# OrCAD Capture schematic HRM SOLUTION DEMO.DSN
size B; title: PSoC 4 BLE HRM Solution Demo; note: -
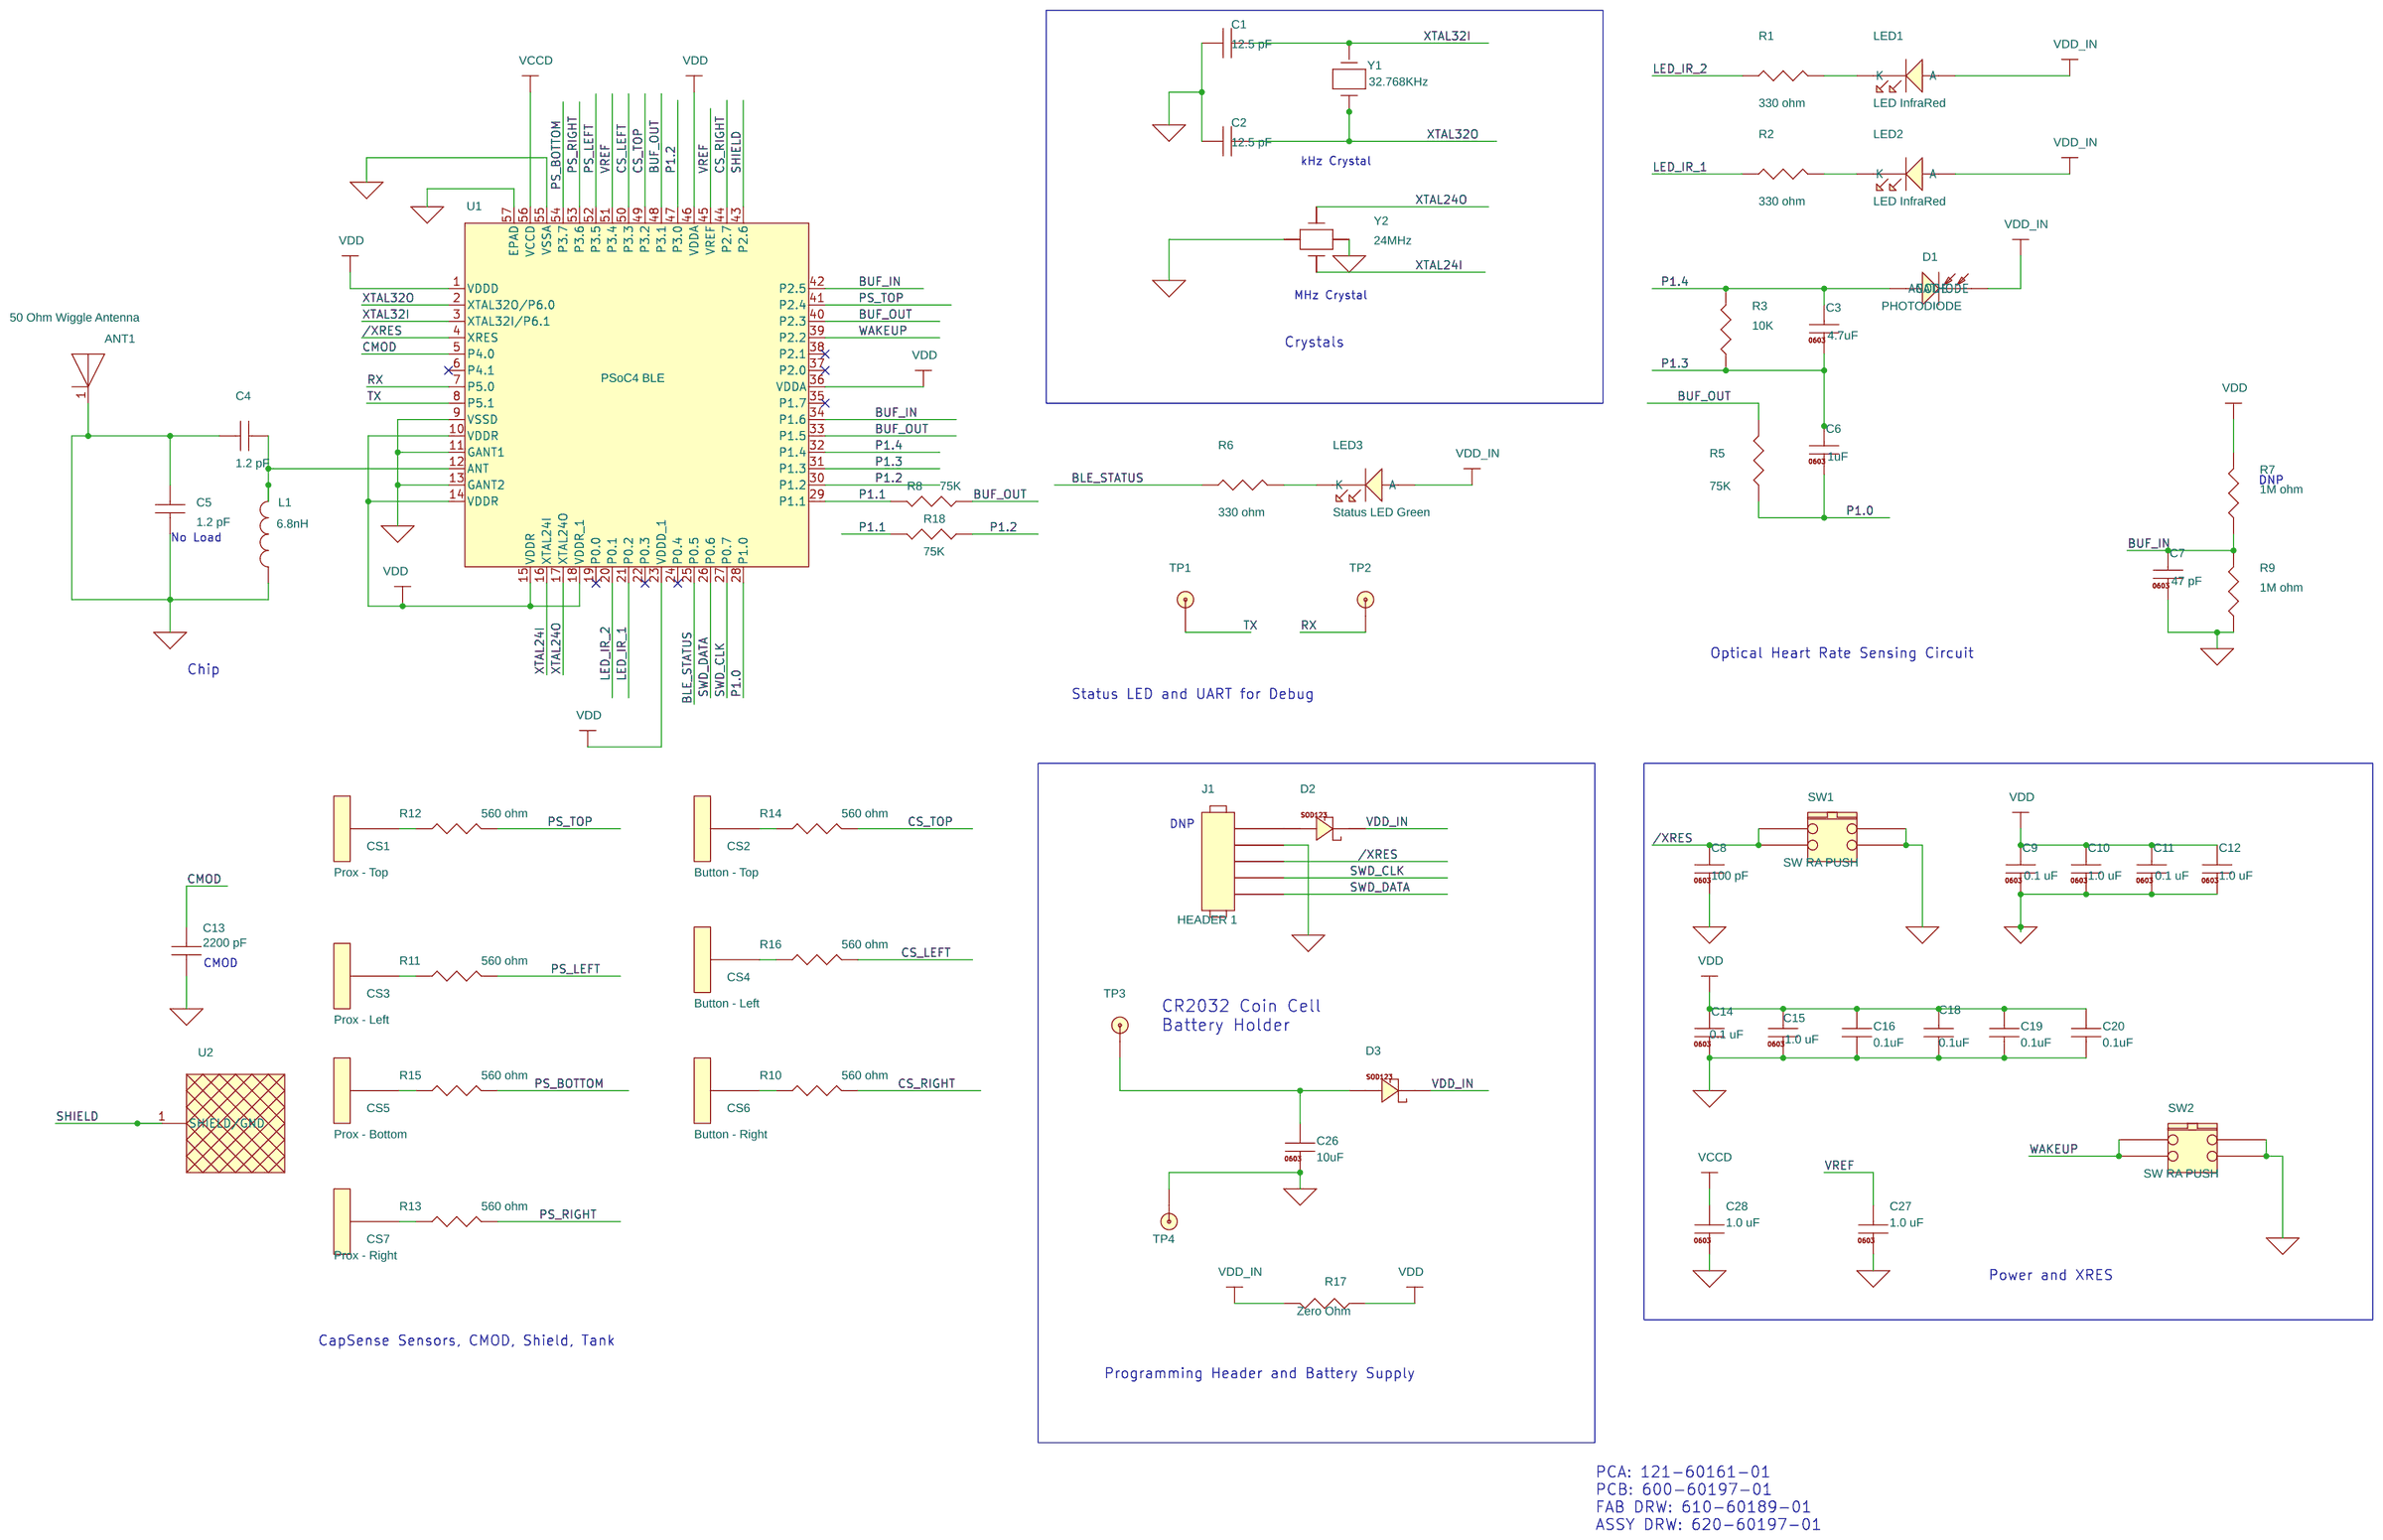
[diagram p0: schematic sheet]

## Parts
ANT1  50 Ohm Wiggle Antenna  [antenna15]
C1  12.5 pF  [C-CC0603]
C2  12.5 pF  [C-CC0603]
C3  4.7uF  [C-CC0603]
C4  1.2 pF  [cc0402]
C5  1.2 pF  [cc0402_1]
C6  1uF  [C-CC0603]
C7  47 pF  [C-CC0603]
C8  100 pF  [C-CC0603]
C9  0.1 uF  [c-cc0402]
C10  1.0 uF  [C-CC0603]
C11  0.1 uF  [c-cc0402]
C12  1.0 uF  [C-CC0603]
C13  2200 pF  [C-CC0603]
C14  0.1 uF  [c-cc0402]
C15  1.0 uF  [C-CC0603]
C16  0.1uF  [C-CC0603]
C18  0.1uF  [C-CC0603]
C19  0.1uF  [C-CC0603]
C20  0.1uF  [C-CC0603]
C26  10uF  [C-CC0603]
C27  1.0 uF  [C-CC0603]
C28  1.0 uF  [C-CC0603]
CS1  Prox - Top  [CAPSENCE]
CS2  Button - Top  [CAPSENCE]
CS3  Prox - Left  [CAPSENCE]
CS4  Button - Left  [CAPSENCE]
CS5  Prox - Bottom  [CAPSENCE]
CS6  Button - Right  [CAPSENCE]
CS7  Prox - Right  [CAPSENCE]
D1  PHOTODIODE  [PHOTO_DIODE]
D2  MBR0520L  [sod123]
D3  MBR0520L  [sod123]
J1  HEADER 1  [HEAD_5_2p54_40X80_420]
L1  6.8nH  [cc0402_1]
LED1  LED InfraRed  [LED]
LED2  LED InfraRed  [LED]
LED3  Status LED Green  [L0805]
R1  330 ohm  [R-CR0603]
R2  330 ohm  [R-CR0603]
R3  10K  [R-CR0603]
R5  75K  [R-CR0603]
R6  330 ohm  [R-CR0603]
R7  1M ohm  [R-CR0603]
R8  75K  [R0402-IPC]
R9  1M ohm  [R-CR0603]
R10  560 ohm  [R0402-IPC]
R11  560 ohm  [R0402-IPC]
R12  560 ohm  [R0402-IPC]
R13  560 ohm  [R0402-IPC]
R14  560 ohm  [R0402-IPC]
R15  560 ohm  [R0402-IPC]
R16  560 ohm  [R0402-IPC]
R17  Zero Ohm  [R-CR0603]
R18  75K  [R0402-IPC]
SW1  SW RA PUSH  [sw_4p_3p6_52x42_54]
SW2  SW RA PUSH  [sw_4p_3p6_52x42_54]
TP1  RED  [TP_48]
TP2  RED  [TP_48]
TP3  RED  [TP_48]
TP4  RED  [TP_48]
U1  PSoC4 BLE  [QFN40P700X700X60-57T570X570N]
U2  HASH GND  [VIA_25X13_SHIELD]
Y1  32.768KHz  [CRY_2_2P6_40X62_32]
Y2  24MHz  [CRY_4_1P7_80X100_22]

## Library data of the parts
ANT1 = Wiggle_Antenna_0
C1 C2 = CAP_NP: CAP CER 12PF 50V 5% NP0 0603; Manufacturer: TDK CORPORATION; Manufacturer Part No: C1608C0G1H120J080AA
C3 C6 C7 = 0_0.1_uFd_0402: CAP CER 47PF 50V 5% NP0 0603; ALT_SYMBOLS: C-CC0603_A; Mfr_Name: TDK CORPORATION; Mfr_Part_Number: C1608C0G1H470J080AA; VOLTAGE: 50V
C4 C5 = CAP: CAP CER 1.2PF 50V NP0 0603; Mfr_Name: SAMSUNG ELECTRO-MECHANICS AMERICA, INC (VA); Mfr_Part_Number: CL10C1R2CB8NNNC; Tolerance: 0.05pF
C8 = 1_0.0_uFd_0603_X5R_25V_10%: CAP CER 100PF 50V 5% NP0 0603; DEVICE: 100pFd_0603 _25V; Mfr_Name: TDK CORPORATION; Mfr_Part_Number: C1608C0G1H101J080AA; Tolerance: 5%; VOLTAGE: 50V
C9 C11 C14 = 0_0.1_uFd_0402: CAP CER 0.1UF 25V 10% X7R 0603; ALT_SYMBOLS: C-CC0603_A; DEVICE: 0p1uFd_0603; Mfr_Name: TDK CORPORATION; Mfr_Part_Number: C1608X7R1E104K080AA; Section: PSoC 4A; VOLTAGE: 25V
C10 C15 C27 C28 = 1_0.0_uFd_0603_X5R_25V_10%: CAP CER 1UF 25V 10% X5R 0603; Mfr_Name: TDK CORPORATION; Mfr_Part_Number: C1608X5R1E105K080AC; VOLTAGE: 25V
C12 = 1_0.0_uFd_0603_X5R_25V_10%: CAP CER 1UF 25V 10% X5R 0603; Mfr_Name: TDK CORPORATION; Mfr_Part_Number: C1608X5R1E105K080AC; Section: PSoC 4A; VOLTAGE: 25V
C13 = CAP: CAP CER 2200PF 50V 10% X7R 0603; Mfr_Name: SAMSUNG ELECTRO-MECHANICS AMERICA, INC (VA); Mfr_Part_Number: CL10B222KB8SFNC; Tolerance: 5%
C16 C18-C20 = CAPACITOR_NON-POL
C26 = 1_0.0_uFd_0603_X5R_25V_10%: CAP CER 10UF 16V 20% X5R 0603; DEVICE: 10uFd_0603_16V; Mfr_Name: MURATA ELECTRONICS; Mfr_Part_Number: GRM188R61C106MA73D; Tolerance: 20%; VOLTAGE: 16V
CS1-CS7 = CapSense_Sensor_0
D1 = PHOTODIODE_1
D2 D3 = TMP_134158: DIODE SCHOTTKY 20V 0.5A SOD123; Digikey: MBR0520LCT-ND
J1 = HEADER_5
L1 = INDUCTOR
LED1 LED2 = LED_Green_0805_0: LED 2.0X1.2MM IR WTR CLEAR 0805; Mfr_Name: SUNLED COMPANY LLC; Mfr_Part_Number: XZTNI54W
LED3 = LED_Green_0805_0: LED GREEN CLEAR 0805 SMD; Mfr_Name: VISUAL COMMUNICATIONS COMPANY, LLC; Mfr_Part_Number: CMD17-21VGC/TR8
R1 R2 = 330_ohm_5%_0805_1: RES 330 OHM 1/10W 5% 0603 SMD; DEVICE: 330oh_0603; Mfr_Name: PANASONIC ELECTRONIC COMPONENTS; Mfr_Part_Number: ERJ-3GEYJ331V; Section: User Interface
R3 R5 R7-R9 R18 = 330_ohm_5%_0805_1: RES 330 OHM 1/10W 5% 0603 SMD; Mfr_Name: PANASONIC ELECTRONIC COMPONENTS; Mfr_Part_Number: ERJ-3GEYJ331V; Section: User Interface
R6 = 330_ohm_5%_0805_1: RES 330 OHM 1/10W 5% 0603 SMD; DEVICE: 330ohm_0603; Mfr_Name: PANASONIC ELECTRONIC COMPONENTS; Mfr_Part_Number: ERJ-3GEYJ331V; Section: User Interface
R10-R16 = RESISTOR: RES 560 OHM 1/10W 5% 0603 SMD; CLASS: DISCRETE; DEVICE: 560_0603; Mfr_Name: Panasonic-ECG; Mfr_Part_Number: ERJ-3GEYJ561V
R17 = 330_ohm_5%_0805_0: RES 0.0 OHM 1/10W JUMP 0603 SMD; Mfr_Name: PANASONIC ELECTRONIC COMPONENTS; Mfr_Part_Number: ERJ-3GEY0R00V; Section: PSoC 4A
SW1 SW2 = Switch_RA_Pushbutton_0: SWITCH TACTILE SPST-NO 0.05A 12V; Mfr_Name: PANASONIC ELECTRONIC COMPONENTS; Mfr_Part_Number: EVQ-P7J01P
TP1-TP4 = TEST_POINT: TEST POINT 43 HOLE 65 PLATED RED; CLASS: DISCRETE; DEVICE: TP-43R_R; Mfr_Name: Keystone Electronics; Mfr_Part_Number: 5000; Package Type: TH; Part Number: 400-00001
U1 = PSoC_BLE_6
U2 = Hash_GND
Y1 = 32_0.768KHz_XTAL_5P: CRYSTAL 32.768KHZ 12.5PF SMD; Mfr_Name: AVX CORP/KYOCERA CORP; Mfr_Part_Number: ST3215SB32768H5HPWAA; Section: PSoC3
Y2 = ZTA_14: CRYSTAL 24MHZ 8PF SMD; Mfr_Name: ECS INC; Mfr_Part_Number: ECS-240-8-36CKM

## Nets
GND_SIGNAL: ANT1.1 C1.2 C2.2 C4.2 C5.1 C5.2 C7.2 C8.2 C9.2 C10.2 C11.2 C12.2 C13.2 C14.2 C15.2 C16.2 C18.2 C19.2 C20.2 C26.2 C27.2 C28.2 J1.2 L1.1 R9.1 SW1.2 SW1.4 SW2.2 SW2.4 TP4.1 U1.9(VSSD) U1.11(GANT1) U1.13(GANT2) U1.55(VSSA) U1.57(EPAD) Y2.2 Y2.4
VCCD: C28.1 U1.56(VCCD)
VDD: C9.1 C10.1 C11.1 C12.1 C14.1 C15.1 C16.1 C18.1 C19.1 C20.1 R7.2 R17.1 U1.1(VDDD) U1.10(VDDR) U1.14(VDDR) U1.15(VDDR) U1.18(VDDR_1) U1.23(VDDD_1) U1.36(VDDA) U1.46(VDDA)
VDD_IN: D1.2(CATHODE) D2.1(CATHODE) D3.1(CATHODE) LED1.2(A) LED2.2(A) LED3.2(A) R17.2
/XRES: C8.1 J1.3 SW1.1 SW1.3 U1.4(XRES)
BLE_STATUS: R6.1 U1.25(P0.5)
BUF_IN: C7.1 R7.1 R9.2 U1.34(P1.6) U1.42(P2.5)
BUF_OUT: R5.2 R8.1 U1.33(P1.5) U1.40(P2.3) U1.48(P3.1)
CMOD: C13.1 U1.5(P4.0)
CS_LEFT: R16.2 U1.50(P3.3)
CS_RIGHT: R10.2 U1.44(P2.7)
CS_TOP: R14.2 U1.49(P3.2)
LED_IR_1: R2.1 U1.21(P0.2)
LED_IR_2: R1.1 U1.20(P0.1)
P1.0: C6.2 R5.1 U1.28(P1.0)
P1.1: R8.2 R18.2 U1.29(P1.1)
P1.2: R18.1 U1.30(P1.2) U1.47(P3.0)
P1.3: C3.2 C6.1 R3.1 U1.31(P1.3)
P1.4: C3.1 D1.1(ANODE) R3.2 U1.32(P1.4)
PS_BOTTOM: R15.2 U1.54(P3.7)
PS_LEFT: R11.2 U1.52(P3.5)
PS_RIGHT: R13.2 U1.53(P3.6)
PS_TOP: R12.2 U1.41(P2.4)
RX: TP2.1 U1.7(P5.0)
SHIELD: U1.43(P2.6) U2.1(SHIELD/GND)
SWD_CLK: J1.4 U1.27(P0.7)
SWD_DATA: J1.5 U1.26(P0.6)
TX: TP1.1 U1.8(P5.1)
VREF: C27.1 U1.45(VREF) U1.51(P3.4)
WAKEUP: SW2.1 SW2.3 U1.39(P2.2)
XTAL24I: U1.16(XTAL24I) Y2.3
XTAL24O: U1.17(XTAL24O) Y2.1
XTAL32I: C1.1 U1.3(XTAL32I/P6.1) Y1.1
XTAL32O: C2.1 U1.2(XTAL32O/P6.0) Y1.2
N05559: LED3.1(K) R6.2
N16776133: CS7.1 R13.1
N16776137: CS1.1 R12.1
N16776145: CS5.1 R15.1
N16776149: CS3.1 R11.1
N16783830: LED2.1(K) R2.2
N16783862: LED1.1(K) R1.2
N16783984: C26.1 D3.2(ANODE) TP3.1
N16844141: CS2.1 R14.1
N16844145: CS4.1 R16.1
N16865210: C4.1 L1.2 U1.12(ANT)
N16879821: CS6.1 R10.1
N16883096: D2.2(ANODE) J1.1

Not connected (* = marked no-connect by the designer): U1 6(P4.1)* 19(P0.0)* 22(P0.3)* 24(P0.4)* 35(P1.7)* 37(P2.0)* 38(P2.1)*

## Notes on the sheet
- kHz Crystal
- MHz Crystal
- Crystals
- DNP
- No Load
- Optical Heart Rate Sensing Circuit
- Chip
- Status LED and UART for Debug
- DNP
- CMOD
- CR2032 Coin Cell
  Battery Holder
- Power and XRES
- CapSense Sensors, CMOD, Shield, Tank
- Programming Header and Battery Supply
- PCA: 121-60161-01
  PCB: 600-60197-01
  FAB DRW: 610-60189-01
  ASSY DRW: 620-60197-01
